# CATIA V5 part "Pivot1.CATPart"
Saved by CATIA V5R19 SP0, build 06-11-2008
Part number: Pivot1
Bounding box of the stored display mesh (mm): x 20 to 30, y 16.5 to 23.5, z -3.329 to 7
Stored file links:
  F:\IAO\Catia\Pivot1.CATPart
  F:\IAO\Catia\Etau.CATProduct
  F:\IAO\Catia\Squelette_pivot.CATPart
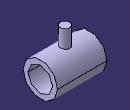
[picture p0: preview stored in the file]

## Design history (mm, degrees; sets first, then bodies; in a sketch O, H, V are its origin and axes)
Set1
  Plane1: linked copy from another document
  Point1: linked copy from another document
Body1 (main body)
  Sketch1 on Plane1, origin (25, 0, 0), H (0, 1, 0), V (0, 0, 1)
    circle A1 centre (20, 0) radius 2.5
    point P1 (20, 0)
    reference projected point E1 (20, 0) from Point1
    circle A2 centre (20, 0) radius 3.5
    point P2 (20, 0)
    reference projected point E2 (20, 0) from Point1
    radius A1 = 2.5
    radius A2 = 3.5
    coincidence: P1 E1, P2 E2
  Pad1: profile Sketch1, direction (1, 0, 0), length 5, mirrored extent
  Sketch2 on Plane1, origin (25, 0, 0), H (0, 1, 0), V (0, 0, 1)
    line L1 (20, 3) -> (19, 3)
    line L2 (19, 3) -> (19, 7)
    line L3 (19, 7) -> (20, 7)
    line L4 (20, 7) -> (20, 3)
    reference projected point E1 (20, 0) from Point1
    reference projected point E2 (20, 0) from Point1
    distance L1 E1 = 3
    length L3 = 1
    distance L4 E2 = 0
    length L2 = 4
    horizontal: L1 H, L3 H
    vertical: L2 V, L4 V
  Shaft1: profile Sketch2, axis Sketch2.L4, angle 360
